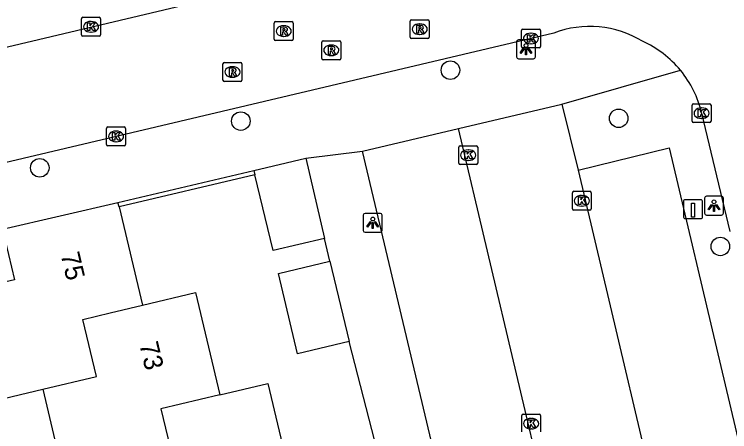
# Model space of a CAD drawing. Extents: x 158038 to 159242, y 380133 to 381214.
# Drawn here: x 158478.81 to 158516.63, y 380493.72 to 380515.79 of the extents above; entities that cross this region are included whole.
import ezdxf

# ---------------------------------------------------------------- set-up
doc = ezdxf.new("R2010")
doc.units = 0
for name, color, linetype in [('IMGEO_Boom', 7, 'Continuous'), ('IMGEO_Kolk', 7, 'Continuous'), ('IMGEO_Laadpaal', 7, 'Continuous'), ('IMGEO_Lichtpunt', 7, 'Continuous'), ('IMGEO_Muur', 7, 'Continuous'), ('IMGEO_Pand', 7, 'Continuous'), ('IMGEO_Pand_nummerreeks', 7, 'Continuous'), ('IMGEO_Rijbaan_lokaal_open', 7, 'Continuous'), ('IMGEO_Rioolput', 7, 'Continuous'), ('IMGEO_Voetpad_open', 7, 'Continuous')]:
    doc.layers.add(name, color=color, linetype=linetype)

msp = doc.modelspace()

# ---------------------------------------------------------------- linework, layer by layer
at = {"layer": 'IMGEO_Boom'}
for centre in [(158501.87, 380512.837), (158510.766, 380510.291), (158490.788, 380510.145), (158480.158, 380507.674), (158516.142, 380503.516)]:
    msp.add_circle(centre, 0.489, dxfattribs=at)
at = {"layer": 'IMGEO_Kolk'}
for p, q in [((158482.367, 380514.705), (158482.367, 380515.557)), ((158482.442, 380515.631), (158483.294, 380515.631)), ((158482.855, 380515.411), (158482.88, 380515.411)), ((158483.368, 380515.557), (158483.368, 380514.705)), ((158505.627, 380514.084), (158505.627, 380514.936)), ((158505.702, 380515.01), (158506.554, 380515.01)), ((158506.628, 380514.936), (158506.628, 380514.084)), ((158483.294, 380514.631), (158482.442, 380514.631)), ((158482.878, 380514.851), (158482.853, 380514.851)), ((158506.115, 380514.79), (158506.14, 380514.79)), ((158506.138, 380514.23), (158506.113, 380514.23)), ((158506.554, 380514.01), (158505.702, 380514.01)), ((158514.648, 380510.137), (158514.648, 380510.989)), ((158514.723, 380511.063), (158515.575, 380511.063)), ((158515.136, 380510.843), (158515.161, 380510.843)), ((158515.649, 380510.989), (158515.649, 380510.137)), ((158515.575, 380510.063), (158514.723, 380510.063)), ((158515.159, 380510.283), (158515.134, 380510.283)), ((158483.689, 380508.909), (158483.689, 380509.761)), ((158483.764, 380509.835), (158484.616, 380509.835)), ((158484.177, 380509.615), (158484.202, 380509.615)), ((158484.69, 380509.761), (158484.69, 380508.909)), ((158484.2, 380509.055), (158484.175, 380509.055)), ((158484.616, 380508.835), (158483.764, 380508.835)), ((158502.311, 380507.917), (158502.311, 380508.769)), ((158502.386, 380508.843), (158503.238, 380508.843)), ((158502.799, 380508.623), (158502.824, 380508.623)), ((158503.312, 380508.769), (158503.312, 380507.917)), ((158503.238, 380507.843), (158502.386, 380507.843)), ((158502.822, 380508.063), (158502.797, 380508.063)), ((158508.318, 380505.506), (158508.318, 380506.358)), ((158508.393, 380506.432), (158509.245, 380506.432)), ((158508.806, 380506.212), (158508.831, 380506.212)), ((158509.319, 380506.358), (158509.319, 380505.506)), ((158508.829, 380505.652), (158508.804, 380505.652)), ((158509.245, 380505.432), (158508.393, 380505.432)), ((158505.637, 380493.724), (158505.637, 380494.576)), ((158505.712, 380494.65), (158506.564, 380494.65)), ((158506.638, 380494.576), (158506.638, 380493.724)), ((158506.125, 380494.43), (158506.15, 380494.43)), ((158506.148, 380493.87), (158506.123, 380493.87))]:
    msp.add_line(p, q, dxfattribs=at)
for points in [[(158482.367, 380514.705), (158482.367, 380515.557)], [(158482.442, 380515.631), (158483.294, 380515.631)], [(158482.688, 380515.331), (158482.811, 380515.331), (158482.811, 380515.18), (158482.941, 380515.331), (158483.105, 380515.331), (158482.959, 380515.18), (158483.112, 380514.931), (158482.96, 380514.931), (158482.875, 380515.095), (158482.811, 380515.028), (158482.811, 380514.931), (158482.688, 380514.931), (158482.688, 380515.331)], [(158483.368, 380515.557), (158483.368, 380514.705)], [(158505.627, 380514.084), (158505.627, 380514.936)], [(158505.702, 380515.01), (158506.554, 380515.01)], [(158506.628, 380514.936), (158506.628, 380514.084)], [(158483.294, 380514.631), (158482.442, 380514.631)], [(158505.948, 380514.71), (158506.071, 380514.71), (158506.071, 380514.559), (158506.201, 380514.71), (158506.365, 380514.71), (158506.219, 380514.559), (158506.372, 380514.31), (158506.22, 380514.31), (158506.135, 380514.474), (158506.071, 380514.407), (158506.071, 380514.31), (158505.948, 380514.31), (158505.948, 380514.71)], [(158506.554, 380514.01), (158505.702, 380514.01)], [(158514.648, 380510.137), (158514.648, 380510.989)], [(158514.723, 380511.063), (158515.575, 380511.063)], [(158514.969, 380510.763), (158515.092, 380510.763), (158515.092, 380510.612), (158515.222, 380510.763), (158515.386, 380510.763), (158515.24, 380510.612), (158515.393, 380510.363), (158515.241, 380510.363), (158515.156, 380510.527), (158515.092, 380510.46), (158515.092, 380510.363), (158514.969, 380510.363), (158514.969, 380510.763)], [(158515.649, 380510.989), (158515.649, 380510.137)], [(158515.575, 380510.063), (158514.723, 380510.063)], [(158483.689, 380508.909), (158483.689, 380509.761)], [(158483.764, 380509.835), (158484.616, 380509.835)], [(158484.69, 380509.761), (158484.69, 380508.909)], [(158484.01, 380509.535), (158484.133, 380509.535), (158484.133, 380509.384), (158484.263, 380509.535), (158484.427, 380509.535), (158484.281, 380509.384), (158484.434, 380509.135), (158484.282, 380509.135), (158484.197, 380509.299), (158484.133, 380509.232), (158484.133, 380509.135), (158484.01, 380509.135), (158484.01, 380509.535)], [(158484.616, 380508.835), (158483.764, 380508.835)], [(158502.311, 380507.917), (158502.311, 380508.769)], [(158502.386, 380508.843), (158503.238, 380508.843)], [(158502.632, 380508.543), (158502.755, 380508.543), (158502.755, 380508.392), (158502.885, 380508.543), (158503.049, 380508.543), (158502.903, 380508.392), (158503.056, 380508.143), (158502.904, 380508.143), (158502.819, 380508.307), (158502.755, 380508.24), (158502.755, 380508.143), (158502.632, 380508.143), (158502.632, 380508.543)], [(158503.312, 380508.769), (158503.312, 380507.917)], [(158503.238, 380507.843), (158502.386, 380507.843)], [(158508.318, 380505.506), (158508.318, 380506.358)], [(158508.393, 380506.432), (158509.245, 380506.432)], [(158509.319, 380506.358), (158509.319, 380505.506)], [(158508.639, 380506.132), (158508.762, 380506.132), (158508.762, 380505.981), (158508.892, 380506.132), (158509.056, 380506.132), (158508.91, 380505.981), (158509.063, 380505.732), (158508.911, 380505.732), (158508.826, 380505.896), (158508.762, 380505.829), (158508.762, 380505.732), (158508.639, 380505.732), (158508.639, 380506.132)], [(158509.245, 380505.432), (158508.393, 380505.432)], [(158505.637, 380493.724), (158505.637, 380494.576)], [(158505.712, 380494.65), (158506.564, 380494.65)], [(158506.638, 380494.576), (158506.638, 380493.724)], [(158505.958, 380494.35), (158506.081, 380494.35), (158506.081, 380494.199), (158506.211, 380494.35), (158506.375, 380494.35), (158506.229, 380494.199), (158506.382, 380493.95), (158506.23, 380493.95), (158506.145, 380494.114), (158506.081, 380494.047), (158506.081, 380493.95), (158505.958, 380493.95), (158505.958, 380494.35)]]:
    msp.add_lwpolyline(points, dxfattribs=at)
for centre, start, end in [((158482.444, 380515.555), 91.552, 178.448), ((158482.444, 380515.555), 91.552, 178.448), ((158483.292, 380515.555), 1.552, 88.448), ((158483.292, 380515.555), 1.552, 88.448), ((158505.704, 380514.934), 91.552, 178.448), ((158505.704, 380514.934), 91.552, 178.448), ((158506.552, 380514.934), 1.552, 88.448), ((158506.552, 380514.934), 1.552, 88.448), ((158482.444, 380514.707), 181.552, 268.448), ((158482.444, 380514.707), 181.552, 268.448), ((158483.292, 380514.707), 271.552, 358.448), ((158483.292, 380514.707), 271.552, 358.448), ((158505.704, 380514.086), 181.552, 268.448), ((158505.704, 380514.086), 181.552, 268.448), ((158506.552, 380514.086), 271.552, 358.448), ((158506.552, 380514.086), 271.552, 358.448), ((158514.725, 380510.987), 91.552, 178.448), ((158514.725, 380510.987), 91.552, 178.448), ((158515.573, 380510.987), 1.552, 88.448), ((158515.573, 380510.987), 1.552, 88.448), ((158514.725, 380510.139), 181.552, 268.448), ((158514.725, 380510.139), 181.552, 268.448), ((158515.573, 380510.139), 271.552, 358.448), ((158515.573, 380510.139), 271.552, 358.448), ((158483.766, 380509.759), 91.552, 178.448), ((158483.766, 380509.759), 91.552, 178.448), ((158484.614, 380509.759), 1.552, 88.448), ((158484.614, 380509.759), 1.552, 88.448), ((158483.766, 380508.911), 181.552, 268.448), ((158483.766, 380508.911), 181.552, 268.448), ((158484.614, 380508.911), 271.552, 358.448), ((158484.614, 380508.911), 271.552, 358.448), ((158502.388, 380508.767), 91.552, 178.448), ((158502.388, 380508.767), 91.552, 178.448), ((158503.236, 380508.767), 1.552, 88.448), ((158503.236, 380508.767), 1.552, 88.448), ((158502.388, 380507.919), 181.552, 268.448), ((158502.388, 380507.919), 181.552, 268.448), ((158503.236, 380507.919), 271.552, 358.448), ((158503.236, 380507.919), 271.552, 358.448), ((158508.395, 380506.356), 91.552, 178.448), ((158508.395, 380506.356), 91.552, 178.448), ((158509.243, 380506.356), 1.552, 88.448), ((158509.243, 380506.356), 1.552, 88.448), ((158508.395, 380505.508), 181.552, 268.448), ((158508.395, 380505.508), 181.552, 268.448), ((158509.243, 380505.508), 271.552, 358.448), ((158509.243, 380505.508), 271.552, 358.448), ((158505.714, 380494.574), 91.552, 178.448), ((158505.714, 380494.574), 91.552, 178.448), ((158506.562, 380494.574), 1.552, 88.448), ((158506.562, 380494.574), 1.552, 88.448)]:
    msp.add_arc(centre, 0.0765, start, end, dxfattribs=at)
for centre, major_axis, ratio, start_param, end_param in [((158482.854, 380515.131), (-0.387, 0.002), 0.722429, 4.712389, 7.853982), ((158482.879, 380515.131), (-0.39, 0.002), 0.717154, 1.570796, 4.712389), ((158506.114, 380514.51), (-0.387, 0.002), 0.722429, 4.712389, 7.853982), ((158506.139, 380514.51), (-0.39, 0.002), 0.717154, 1.570796, 4.712389), ((158515.135, 380510.563), (-0.387, 0.002), 0.722429, 4.712389, 7.853982), ((158515.16, 380510.563), (-0.39, 0.002), 0.717154, 1.570796, 4.712389), ((158484.176, 380509.335), (-0.387, 0.002), 0.722429, 4.712389, 7.853982), ((158484.201, 380509.335), (-0.39, 0.002), 0.717154, 1.570796, 4.712389), ((158502.798, 380508.343), (-0.387, 0.002), 0.722429, 4.712389, 7.853982), ((158502.823, 380508.343), (-0.39, 0.002), 0.717154, 1.570796, 4.712389), ((158508.805, 380505.932), (-0.387, 0.002), 0.722429, 4.712389, 7.853982), ((158508.83, 380505.932), (-0.39, 0.002), 0.717154, 1.570796, 4.712389), ((158506.124, 380494.15), (-0.387, 0.002), 0.722429, 4.712389, 7.853982), ((158506.149, 380494.15), (-0.39, 0.002), 0.717154, 1.570796, 4.712389)]:
    msp.add_ellipse(centre, major_axis=major_axis, ratio=ratio, start_param=start_param, end_param=end_param, dxfattribs=at)
at = {"layer": 'IMGEO_Laadpaal'}
for p, q in [((158514.195, 380505.905), (158514.195, 380505.064)), ((158514.195, 380505.905), (158514.195, 380505.064)), ((158515.111, 380505.989), (158514.27, 380505.989)), ((158515.111, 380505.989), (158514.27, 380505.989)), ((158515.195, 380505.073), (158515.195, 380505.914)), ((158515.195, 380505.073), (158515.195, 380505.914)), ((158514.279, 380504.989), (158515.12, 380504.989)), ((158514.279, 380504.989), (158515.12, 380504.989))]:
    msp.add_line(p, q, dxfattribs=at)
msp.add_lwpolyline([(158514.61, 380505.802), (158514.77, 380505.802), (158514.77, 380505.069), (158514.61, 380505.069), (158514.61, 380505.802)], dxfattribs=at)
for centre, start, end in [((158514.273, 380505.911), 92.4484, 184.2845), ((158514.273, 380505.911), 92.4484, 184.2845), ((158515.117, 380505.911), 2.4484, 94.2845), ((158515.117, 380505.911), 2.4484, 94.2845), ((158514.273, 380505.067), 182.4484, 274.2845), ((158514.273, 380505.067), 182.4484, 274.2845), ((158515.117, 380505.067), 272.4484, 4.2845), ((158515.117, 380505.067), 272.4484, 4.2845)]:
    msp.add_arc(centre, 0.0779, start, end, dxfattribs=at)
at = {"layer": 'IMGEO_Lichtpunt'}
for p, q in [((158505.367, 380514.345), (158505.367, 380513.538)), ((158505.367, 380514.345), (158505.367, 380513.538)), ((158506.269, 380514.44), (158505.461, 380514.44)), ((158506.269, 380514.44), (158505.461, 380514.44)), ((158506.363, 380513.538), (158506.363, 380514.345)), ((158506.363, 380513.538), (158506.363, 380514.345)), ((158505.461, 380513.444), (158506.269, 380513.444)), ((158505.461, 380513.444), (158506.269, 380513.444)), ((158515.306, 380506.077), (158515.306, 380505.27)), ((158515.306, 380506.077), (158515.306, 380505.27)), ((158516.208, 380506.172), (158515.4, 380506.172)), ((158516.208, 380506.172), (158515.4, 380506.172)), ((158516.302, 380505.27), (158516.302, 380506.077)), ((158516.302, 380505.27), (158516.302, 380506.077)), ((158497.264, 380505.169), (158497.264, 380504.362)), ((158497.264, 380505.169), (158497.264, 380504.362)), ((158498.166, 380505.264), (158497.358, 380505.264)), ((158498.166, 380505.264), (158497.358, 380505.264)), ((158498.26, 380504.362), (158498.26, 380505.169)), ((158498.26, 380504.362), (158498.26, 380505.169)), ((158515.4, 380505.176), (158516.208, 380505.176)), ((158515.4, 380505.176), (158516.208, 380505.176)), ((158497.358, 380504.268), (158498.166, 380504.268)), ((158497.358, 380504.268), (158498.166, 380504.268))]:
    msp.add_line(p, q, dxfattribs=at)
for points in [[(158505.741, 380514.009), (158505.78, 380513.981), (158505.592, 380513.719), (158505.554, 380513.746), (158505.741, 380514.009)], [(158505.843, 380513.961), (158505.89, 380513.961), (158505.89, 380513.639), (158505.843, 380513.639), (158505.843, 380513.961)], [(158505.953, 380513.981), (158505.991, 380514.008), (158506.178, 380513.746), (158506.139, 380513.718), (158505.953, 380513.981)], [(158515.68, 380505.741), (158515.719, 380505.713), (158515.531, 380505.451), (158515.493, 380505.478), (158515.68, 380505.741)], [(158515.782, 380505.693), (158515.829, 380505.693), (158515.829, 380505.371), (158515.782, 380505.371), (158515.782, 380505.693)], [(158515.892, 380505.713), (158515.93, 380505.74), (158516.117, 380505.478), (158516.078, 380505.45), (158515.892, 380505.713)], [(158497.638, 380504.833), (158497.677, 380504.805), (158497.489, 380504.543), (158497.451, 380504.57), (158497.638, 380504.833)], [(158497.74, 380504.785), (158497.787, 380504.785), (158497.787, 380504.463), (158497.74, 380504.463), (158497.74, 380504.785)], [(158497.85, 380504.805), (158497.888, 380504.832), (158498.075, 380504.57), (158498.036, 380504.542), (158497.85, 380504.805)]]:
    msp.add_lwpolyline(points, dxfattribs=at)
for centre in [(158505.866, 380514.143), (158515.805, 380505.875), (158497.763, 380504.967)]:
    msp.add_circle(centre, 0.0994, dxfattribs=at)
for centre, start, end in [((158505.461, 380514.345), 90, 180), ((158505.461, 380514.345), 90, 180), ((158506.269, 380514.345), 0, 90), ((158506.269, 380514.345), 0, 90), ((158505.461, 380513.538), 180, 270), ((158505.461, 380513.538), 180, 270), ((158506.269, 380513.538), 270, 0), ((158506.269, 380513.538), 270, 360), ((158515.4, 380506.077), 90, 180), ((158515.4, 380506.077), 90, 180), ((158516.208, 380506.077), 0, 90), ((158516.208, 380506.077), 0, 90), ((158497.358, 380505.169), 90, 180), ((158497.358, 380505.169), 90, 180), ((158498.166, 380505.169), 0, 90), ((158498.166, 380505.169), 0, 90), ((158515.4, 380505.27), 180, 270), ((158515.4, 380505.27), 180, 270), ((158516.208, 380505.27), 270, 0), ((158516.208, 380505.27), 270, 360), ((158497.358, 380504.362), 180, 270), ((158497.358, 380504.362), 180, 270), ((158498.166, 380504.362), 270, 0), ((158498.166, 380504.362), 270, 360)]:
    msp.add_arc(centre, 0.0946, start, end, dxfattribs=at)
at = {"layer": 'IMGEO_Muur'}
for points in [[(158484.293, 380505.842), (158491.475, 380507.534)], [(158491.531, 380507.301), (158484.349, 380505.608)]]:
    msp.add_lwpolyline(points, dxfattribs=at)
at = {"layer": 'IMGEO_Pand'}
for points in [[(158491.475, 380507.534), (158494.222, 380508.184)], [(158494.222, 380508.184), (158495.219, 380503.941)], [(158491.475, 380507.534), (158491.531, 380507.301)], [(158495.219, 380503.941), (158492.494, 380503.301), (158491.531, 380507.301)], [(158478.183, 380504.432), (158484.293, 380505.842)], [(158484.349, 380505.608), (158484.293, 380505.842)], [(158484.349, 380505.608), (158485.582, 380500.413)], [(158478.183, 380504.432), (158478.817, 380501.76), (158476.075, 380501.111), (158476.334, 380500), (158477.437, 380495.279), (158480.319, 380495.964)], [(158496.511, 380498.49), (158493.787, 380497.841), (158492.777, 380502.082), (158495.501, 380502.731)], [(158495.501, 380502.731), (158496.511, 380498.49)], [(158485.582, 380500.413), (158488.396, 380501.081), (158489.68, 380495.674)], [(158480.319, 380495.964), (158483.16, 380496.639), (158482.441, 380499.662), (158483.874, 380500), (158485.582, 380500.413)], [(158489.68, 380495.674), (158492.221, 380496.278), (158493.509, 380490.86), (158494.799, 380491.167), (158495.491, 380488.258)], [(158480.319, 380495.964), (158481.615, 380490.515), (158484.416, 380491.181)], [(158489.68, 380495.674), (158486.565, 380494.94), (158487.296, 380491.866), (158484.416, 380491.181)]]:
    msp.add_lwpolyline(points, dxfattribs=at)
at = {"layer": 'IMGEO_Rijbaan_lokaal_open'}
for points in [[(158506.04, 380520.636), (158504.031, 380520.134), (158498.266, 380518.753), (158463.908, 380510.622)], [(158507.333, 380514.796), (158465.242, 380504.854)], [(158502.303, 380509.746), (158507.759, 380511.04)], [(158507.759, 380511.04), (158508.621, 380507.557)], [(158515.149, 380510.563), (158516.649, 380504.3)], [(158509.959, 380477.328), (158502.303, 380509.746)], [(158508.621, 380507.557), (158514.076, 380484.47), (158518.89, 380485.617)]]:
    msp.add_lwpolyline(points, dxfattribs=at)
for centre, radius, start, end in [((158509.24, 380509.796), 5.351, 58.6483, 110.877), ((158509.757, 380509.317), 5.535, 39.4148, 65.8211), ((158509.756, 380509.318), 5.534, 12.9996, 39.4007)]:
    msp.add_arc(centre, radius, start, end, dxfattribs=at)
at = {"layer": 'IMGEO_Rioolput'}
for p, q in [((158492.554, 380514.477), (158492.554, 380515.329)), ((158492.629, 380515.403), (158493.481, 380515.403)), ((158493.555, 380515.329), (158493.555, 380514.477)), ((158499.744, 380514.58), (158499.744, 380515.432)), ((158499.819, 380515.506), (158500.671, 380515.506)), ((158500.232, 380515.286), (158500.257, 380515.286)), ((158500.745, 380515.432), (158500.745, 380514.58)), ((158493.042, 380515.183), (158493.067, 380515.183)), ((158493.065, 380514.623), (158493.04, 380514.623)), ((158500.255, 380514.726), (158500.23, 380514.726)), ((158493.481, 380514.403), (158492.629, 380514.403)), ((158495.072, 380513.461), (158495.072, 380514.313)), ((158495.147, 380514.387), (158495.999, 380514.387)), ((158495.56, 380514.167), (158495.585, 380514.167)), ((158496.073, 380514.313), (158496.073, 380513.461)), ((158500.671, 380514.506), (158499.819, 380514.506)), ((158495.999, 380513.387), (158495.147, 380513.387)), ((158495.583, 380513.607), (158495.558, 380513.607)), ((158489.843, 380512.315), (158489.843, 380513.167)), ((158489.918, 380513.241), (158490.77, 380513.241)), ((158490.331, 380513.021), (158490.356, 380513.021)), ((158490.844, 380513.167), (158490.844, 380512.315)), ((158490.354, 380512.461), (158490.329, 380512.461)), ((158490.77, 380512.241), (158489.918, 380512.241))]:
    msp.add_line(p, q, dxfattribs=at)
for points in [[(158492.554, 380514.477), (158492.554, 380515.329)], [(158492.629, 380515.403), (158493.481, 380515.403)], [(158493.555, 380515.329), (158493.555, 380514.477)], [(158499.744, 380514.58), (158499.744, 380515.432)], [(158499.819, 380515.506), (158500.671, 380515.506)], [(158500.745, 380515.432), (158500.745, 380514.58)], [(158493.143, 380515.101), (158492.891, 380515.103), (158492.891, 380514.703)], [(158493.069, 380515.022), (158493.015, 380515.022), (158493.015, 380514.941)], [(158493.015, 380514.941), (158493.067, 380514.941)], [(158500.333, 380515.204), (158500.081, 380515.206), (158500.081, 380514.806)], [(158500.081, 380514.806), (158500.205, 380514.806), (158500.205, 380514.968), (158500.216, 380514.968)], [(158500.259, 380515.125), (158500.205, 380515.125), (158500.205, 380515.044)], [(158500.205, 380515.044), (158500.257, 380515.044)], [(158500.263, 380514.939), (158500.334, 380514.806), (158500.474, 380514.806), (158500.409, 380514.932)], [(158492.891, 380514.703), (158493.015, 380514.703), (158493.015, 380514.865), (158493.026, 380514.865)], [(158493.073, 380514.836), (158493.144, 380514.703), (158493.284, 380514.703), (158493.219, 380514.829)], [(158493.481, 380514.403), (158492.629, 380514.403)], [(158495.072, 380513.461), (158495.072, 380514.313)], [(158495.147, 380514.387), (158495.999, 380514.387)], [(158496.073, 380514.313), (158496.073, 380513.461)], [(158500.671, 380514.506), (158499.819, 380514.506)], [(158495.661, 380514.085), (158495.409, 380514.087), (158495.409, 380513.687)], [(158495.409, 380513.687), (158495.533, 380513.687), (158495.533, 380513.849), (158495.544, 380513.849)], [(158495.587, 380514.006), (158495.533, 380514.006), (158495.533, 380513.925)], [(158495.533, 380513.925), (158495.585, 380513.925)], [(158495.591, 380513.82), (158495.662, 380513.687), (158495.802, 380513.687), (158495.737, 380513.813)], [(158495.999, 380513.387), (158495.147, 380513.387)], [(158489.843, 380512.315), (158489.843, 380513.167)], [(158489.918, 380513.241), (158490.77, 380513.241)], [(158490.844, 380513.167), (158490.844, 380512.315)], [(158490.432, 380512.939), (158490.18, 380512.941), (158490.18, 380512.541)], [(158490.18, 380512.541), (158490.304, 380512.541), (158490.304, 380512.703), (158490.315, 380512.703)], [(158490.358, 380512.86), (158490.304, 380512.86), (158490.304, 380512.779)], [(158490.304, 380512.779), (158490.356, 380512.779)], [(158490.362, 380512.674), (158490.433, 380512.541), (158490.573, 380512.541), (158490.508, 380512.667)], [(158490.77, 380512.241), (158489.918, 380512.241)]]:
    msp.add_lwpolyline(points, dxfattribs=at)
for centre, radius, start, end in [((158492.631, 380515.327), 0.0765, 91.552, 178.448), ((158492.631, 380515.327), 0.0765, 91.552, 178.448), ((158493.479, 380515.327), 0.0765, 1.552, 88.448), ((158493.479, 380515.327), 0.0765, 1.552, 88.448), ((158499.821, 380515.43), 0.0765, 91.552, 178.448), ((158499.821, 380515.43), 0.0765, 91.552, 178.448), ((158500.669, 380515.43), 0.0765, 1.552, 88.448), ((158500.669, 380515.43), 0.0765, 1.552, 88.448), ((158493.051, 380515.13), 0.19, 274.7715, 282.9687), ((158493.075, 380514.926), 0.0964, 77.0061, 93.1865), ((158493.089, 380514.983), 0.0378, 276.6634, 79.6772), ((158493.142, 380514.991), 0.109, 350.3612, 89.416), ((158493.14, 380514.991), 0.112, 277.5842, 350.9817), ((158500.215, 380514.915), 0.0533, 26.0293, 88.6989), ((158500.241, 380515.233), 0.19, 274.7715, 282.9687), ((158500.265, 380515.029), 0.0964, 77.0061, 93.1865), ((158500.279, 380515.086), 0.0378, 276.6634, 79.6772), ((158500.332, 380515.094), 0.109, 350.3612, 89.416), ((158500.33, 380515.094), 0.112, 277.5842, 350.9817), ((158500.314, 380514.879), 0.108, 29.5134, 73.7905), ((158493.025, 380514.812), 0.0533, 26.0293, 88.6989), ((158493.124, 380514.776), 0.108, 29.5134, 73.7905), ((158499.821, 380514.582), 0.0765, 181.552, 268.448), ((158499.821, 380514.582), 0.0765, 181.552, 268.448), ((158500.669, 380514.582), 0.0765, 271.552, 358.448), ((158500.669, 380514.582), 0.0765, 271.552, 358.448), ((158492.631, 380514.479), 0.0765, 181.552, 268.448), ((158492.631, 380514.479), 0.0765, 181.552, 268.448), ((158493.479, 380514.479), 0.0765, 271.552, 358.448), ((158493.479, 380514.479), 0.0765, 271.552, 358.448), ((158495.149, 380514.311), 0.0765, 91.552, 178.448), ((158495.149, 380514.311), 0.0765, 91.552, 178.448), ((158495.997, 380514.311), 0.0765, 1.552, 88.448), ((158495.997, 380514.311), 0.0765, 1.552, 88.448), ((158495.543, 380513.796), 0.0533, 26.0293, 88.6989), ((158495.569, 380514.114), 0.19, 274.7715, 282.9687), ((158495.593, 380513.91), 0.0964, 77.0061, 93.1865), ((158495.607, 380513.967), 0.0378, 276.6634, 79.6772), ((158495.66, 380513.975), 0.109, 350.3612, 89.416), ((158495.658, 380513.975), 0.112, 277.5842, 350.9817), ((158495.642, 380513.76), 0.108, 29.5134, 73.7905), ((158495.149, 380513.463), 0.0765, 181.552, 268.448), ((158495.149, 380513.463), 0.0765, 181.552, 268.448), ((158495.997, 380513.463), 0.0765, 271.552, 358.448), ((158495.997, 380513.463), 0.0765, 271.552, 358.448), ((158489.92, 380513.165), 0.0765, 91.552, 178.448), ((158489.92, 380513.165), 0.0765, 91.552, 178.448), ((158490.768, 380513.165), 0.0765, 1.552, 88.448), ((158490.768, 380513.165), 0.0765, 1.552, 88.448), ((158490.314, 380512.65), 0.0533, 26.0293, 88.6989), ((158490.34, 380512.968), 0.19, 274.7715, 282.9687), ((158490.364, 380512.764), 0.0964, 77.0061, 93.1865), ((158490.378, 380512.821), 0.0378, 276.6634, 79.6772), ((158490.431, 380512.829), 0.109, 350.3612, 89.416), ((158490.429, 380512.829), 0.112, 277.5842, 350.9817), ((158490.413, 380512.614), 0.108, 29.5134, 73.7905), ((158489.92, 380512.317), 0.0765, 181.552, 268.448), ((158489.92, 380512.317), 0.0765, 181.552, 268.448), ((158490.768, 380512.317), 0.0765, 271.552, 358.448), ((158490.768, 380512.317), 0.0765, 271.552, 358.448)]:
    msp.add_arc(centre, radius, start, end, dxfattribs=at)
for centre, major_axis, ratio, start_param, end_param in [((158500.231, 380515.006), (-0.387, 0.002), 0.722429, 4.712389, 7.853982), ((158500.256, 380515.006), (-0.39, 0.002), 0.717154, 1.570796, 4.712389), ((158493.041, 380514.903), (-0.387, 0.002), 0.722429, 4.712389, 7.853982), ((158493.066, 380514.903), (-0.39, 0.002), 0.717154, 1.570796, 4.712389), ((158495.559, 380513.887), (-0.387, 0.002), 0.722429, 4.712389, 7.853982), ((158495.584, 380513.887), (-0.39, 0.002), 0.717154, 1.570796, 4.712389), ((158490.33, 380512.741), (-0.387, 0.002), 0.722429, 4.712389, 7.853982), ((158490.355, 380512.741), (-0.39, 0.002), 0.717154, 1.570796, 4.712389)]:
    msp.add_ellipse(centre, major_axis=major_axis, ratio=ratio, start_param=start_param, end_param=end_param, dxfattribs=at)
at = {"layer": 'IMGEO_Voetpad_open'}
for points in [[(158507.759, 380511.04), (158514.033, 380512.831)], [(158497.228, 380508.556), (158502.303, 380509.746)], [(158494.222, 380508.184), (158497.228, 380508.556)], [(158509.959, 380477.328), (158504.921, 380476.108), (158497.228, 380508.556)], [(158508.621, 380507.557), (158513.426, 380508.729), (158518.89, 380485.617)], [(158495.501, 380502.731), (158495.219, 380503.941)], [(158497.87, 380493.219), (158496.511, 380498.49)]]:
    msp.add_lwpolyline(points, dxfattribs=at)

# ---------------------------------------------------------------- texts
at = {"layer": 'IMGEO_Pand_nummerreeks'}
for s, rotation, p in [('75', 283.3222, (158481.254, 380503.098)), ('73', 283.47, (158485.412, 380498.353))]:
    msp.add_text(s, height=1, rotation=rotation, dxfattribs=at).set_placement(p)

doc.saveas('drawing.dxf')
